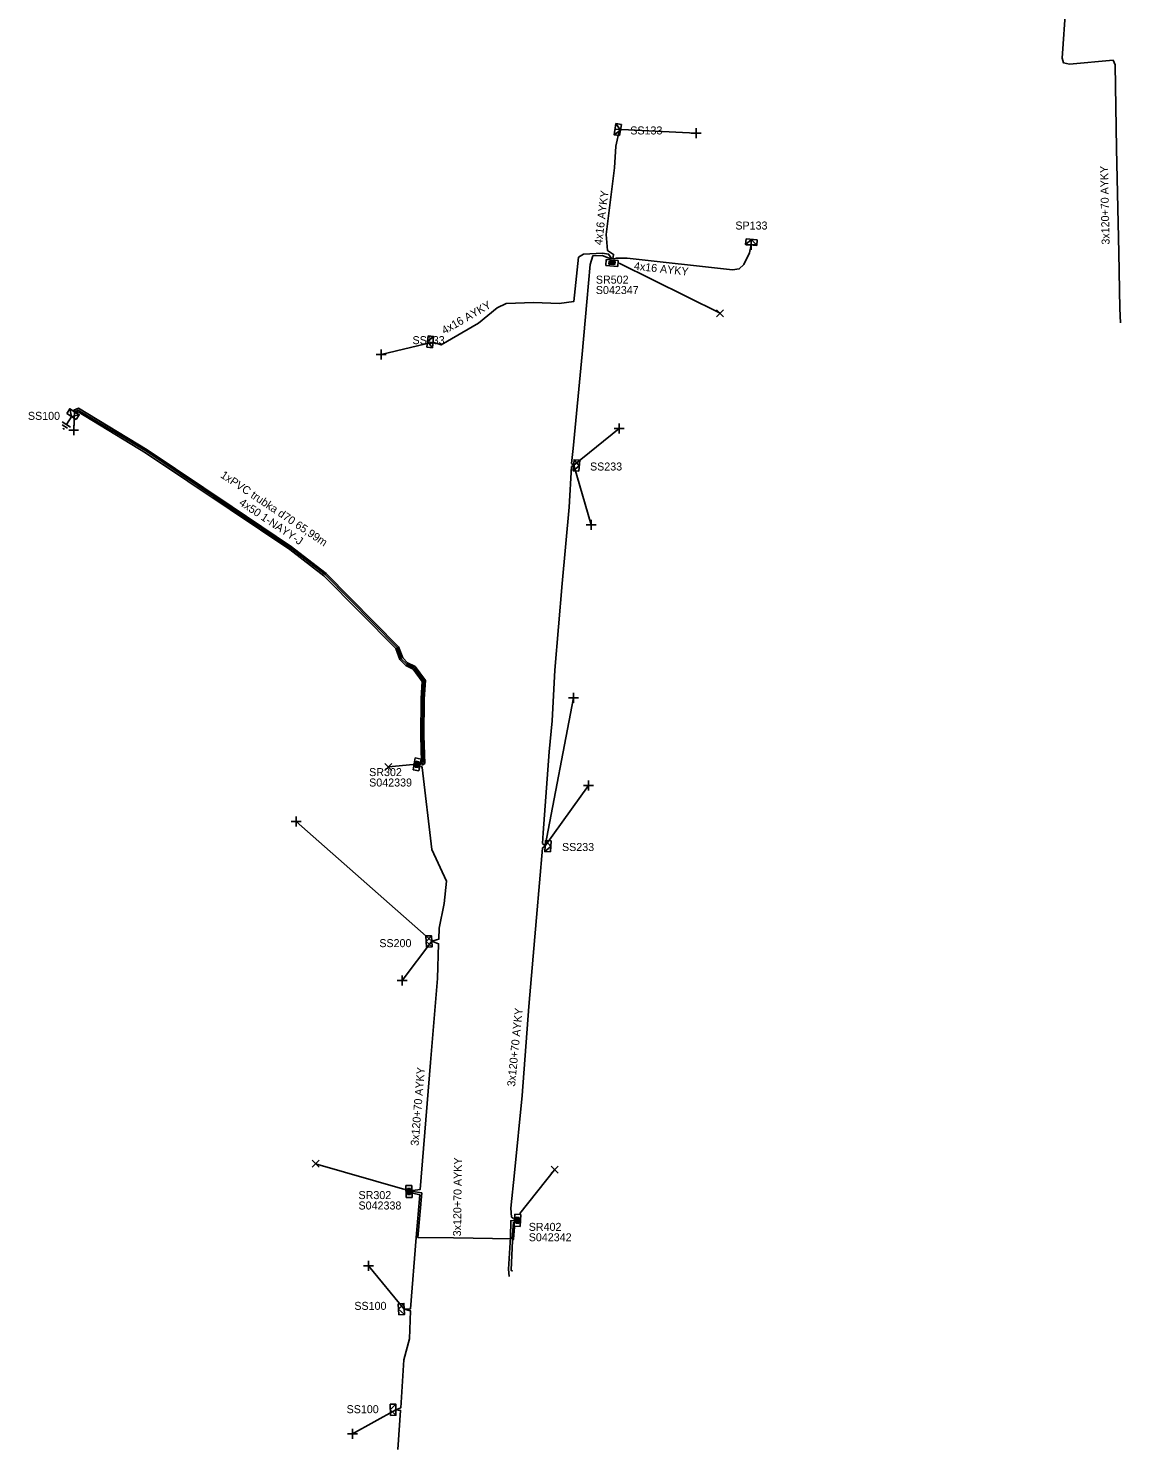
# Model space of a CAD drawing. Extents: x -737417 to -734469, y -1145580 to -1142703.
# Drawn here: x -736731.5 to -736594.9, y -1144630.5 to -1144452.9 of the extents above; entities that cross this region are included whole.
import ezdxf

# ---------------------------------------------------------------- set-up
doc = ezdxf.new("R2010")
doc.units = 0
for name, color, linetype in [('Vrstva 1', 7, 'Continuous'), ('Vrstva 14', 7, 'Continuous'), ('Vrstva 15', 7, 'Continuous'), ('Vrstva 20', 7, 'Continuous'), ('Vrstva 21', 7, 'Continuous'), ('Vrstva 28', 7, 'Continuous'), ('Vrstva 29', 7, 'Continuous'), ('Vrstva 30', 7, 'Continuous'), ('Vrstva 31', 7, 'Continuous'), ('Vrstva 33', 7, 'Continuous'), ('Vrstva 34', 7, 'Continuous'), ('Vrstva 5', 7, 'Continuous'), ('Vrstva 52', 7, 'Continuous'), ('Vrstva 54', 7, 'Continuous'), ('Vrstva 59', 7, 'Continuous'), ('Vrstva 6', 7, 'Continuous'), ('Vrstva 8', 7, 'Continuous'), ('Vrstva 9', 7, 'Continuous')]:
    doc.layers.add(name, color=color, linetype=linetype)

# ---------------------------------------------------------------- blocks, each defined once
blk = doc.blocks.new('NN800')
at = {"layer": 'Vrstva 1'}
for points in [[(-0.44, 0.44), (0.44, -0.44)], [(-0.44, -0.44), (0.44, 0.44)]]:
    blk.add_lwpolyline(points, dxfattribs=at)
blk = doc.blocks.new('NN620')
at = {"layer": 'Vrstva 8'}
for points in [[(0.75, 0), (-0.75, 0)], [(-0.75, 0), (-0.75, -0.75)], [(0.75, -0.75), (0.75, 0)], [(-0.75, -0.75), (0.75, -0.75)], [(0.37, -0.18), (-0.38, -0.18)], [(-0.38, -0.18), (-0.38, -0.56)], [(-0.38, -0.56), (0.37, -0.56)], [(0.32, -0.23), (-0.33, -0.23)], [(-0.33, -0.23), (-0.33, -0.51)], [(-0.33, -0.51), (0.32, -0.51)], [(0.27, -0.27), (-0.28, -0.27)], [(-0.28, -0.27), (-0.28, -0.46)], [(-0.28, -0.46), (0.27, -0.46)], [(0.23, -0.32), (-0.23, -0.32)], [(-0.23, -0.32), (-0.23, -0.42)], [(-0.23, -0.42), (0.23, -0.42)], [(-0.19, -0.37), (0.19, -0.37)], [(0.23, -0.42), (0.23, -0.32)], [(0.27, -0.46), (0.27, -0.27)], [(0.32, -0.51), (0.32, -0.23)], [(0.37, -0.56), (0.37, -0.18)]]:
    blk.add_lwpolyline(points, dxfattribs=at)
blk = doc.blocks.new('NN630')
at = {"layer": 'Vrstva 9'}
for points in [[(0, -0.7), (-0.7, 0)], [(-0.7, -0.7), (-0.7, 0), (0.7, 0), (0.7, -0.7)], [(-0.7, -0.7), (0.7, -0.7)], [(0, -0.7), (0.7, 0)]]:
    blk.add_lwpolyline(points, dxfattribs=at)
blk = doc.blocks.new('NN810')
at = {"layer": 'Vrstva 14'}
for points in [[(0, -0.64), (0, -1.89)], [(0.63, -1.89), (-0.62, -1.89)], [(0.39, -2.2), (-0.4, -2.2)], [(0, -2.52), (-0.12, -2.52)], [(0.14, -2.52), (0, -2.52)]]:
    blk.add_lwpolyline(points, dxfattribs=at)

msp = doc.modelspace()

# ---------------------------------------------------------------- linework, layer by layer
at = {"layer": 'Vrstva 20'}
msp.add_lwpolyline([(-736725.63, -1144500.97), (-736725.79, -1144500.61), (-736725.22, -1144500.37), (-736716.61, -1144505.57), (-736706.01, -1144512.68), (-736698.56, -1144517.67), (-736694.26, -1144520.99), (-736685.19, -1144530.16), (-736684.68, -1144531.55), (-736684.06, -1144532.17), (-736683.12, -1144532.62), (-736681.83, -1144534.38), (-736681.98, -1144536.65), (-736682.02, -1144541.27), (-736681.93, -1144544.74), (-736682.18, -1144544.93), (-736682.42, -1144544.61), (-736682.33, -1144544.54), (-736682.42, -1144541.27), (-736682.38, -1144536.63), (-736682.23, -1144534.5), (-736683.38, -1144532.94), (-736684.3, -1144532.51), (-736685.02, -1144531.77), (-736685.53, -1144530.38), (-736694.52, -1144521.29), (-736698.8, -1144517.99), (-736706.23, -1144513.02), (-736716.83, -1144505.91), (-736725.26, -1144500.81)], close=True, dxfattribs=at)
at = {"layer": 'Vrstva 5'}
for points in [[(-736594.93, -1144489.69), (-736595.02, -1144487.91), (-736595.16, -1144480.95), (-736595.43, -1144467.91), (-736595.62, -1144457.47), (-736595.88, -1144456.88), (-736601.32, -1144457.36), (-736602.06, -1144457.22), (-736602.25, -1144456.63), (-736601.78, -1144450.05), (-736601.32, -1144447.49), (-736600.13, -1144443.42), (-736598.57, -1144440), (-736598.05, -1144438.72), (-736598.27, -1144438.36)], [(-736658.67, -1144481.69), (-736659.73, -1144481.27), (-736660.91, -1144481.32), (-736661.24, -1144482.38), (-736661.64, -1144487.07), (-736662.24, -1144493.62), (-736663.37, -1144505.4), (-736663.56, -1144507.25), (-736663.3, -1144507.49), (-736663.59, -1144507.64), (-736663.86, -1144512.7), (-736664.74, -1144522.26), (-736665.66, -1144533.09), (-736666, -1144539.42), (-736666.36, -1144543.27), (-736667.13, -1144553.42), (-736667.19, -1144554.74), (-736666.86, -1144555.05), (-736667.22, -1144555.31), (-736667.97, -1144563.97), (-736668.89, -1144575.1), (-736669.75, -1144586.22), (-736670.72, -1144595.89), (-736671.16, -1144600.32), (-736671.06, -1144601.42), (-736670.82, -1144601.59)], [(-736682.36, -1144544.82), (-736682.13, -1144544.64), (-736682.22, -1144541.27), (-736682.18, -1144536.64), (-736682.03, -1144534.44), (-736683.25, -1144532.78), (-736684.18, -1144532.34), (-736684.85, -1144531.66), (-736685.36, -1144530.27), (-736694.39, -1144521.14), (-736698.68, -1144517.83), (-736706.12, -1144512.85), (-736716.72, -1144505.74), (-736725.24, -1144500.59), (-736725.71, -1144500.79)], [(-736682.36, -1144545.04), (-736682.26, -1144545.23), (-736681.02, -1144555.48), (-736679.21, -1144559.46), (-736679.48, -1144562.24), (-736680.1, -1144565.3), (-736680.18, -1144566.71), (-736681.05, -1144566.96), (-736680.2, -1144567.27), (-736680.32, -1144571.62), (-736681.21, -1144582.09), (-736682.51, -1144597.99), (-736683.4, -1144598.08)], [(-736683.4, -1144598.41), (-736682.52, -1144598.65), (-736683, -1144603.95), (-736683.7, -1144612.87), (-736684.5, -1144612.91), (-736683.71, -1144613.13), (-736683.83, -1144616.62), (-736684.53, -1144619.27), (-736684.92, -1144625.25), (-736685.53, -1144625.48), (-736684.94, -1144625.57), (-736685.29, -1144630.47)], [(-736683.4, -1144598.23), (-736682.29, -1144598.4), (-736682.8, -1144603.95), (-736678.31, -1144604.03), (-736671.01, -1144604.14), (-736670.82, -1144602.04)], [(-736671.37, -1144608.84), (-736671.43, -1144607.91), (-736671.22, -1144603.91), (-736671.17, -1144601.88), (-736670.83, -1144601.85)]]:
    msp.add_lwpolyline(points, dxfattribs=at)
at = {"layer": 'Vrstva 52'}
for points in [[(-736658.41, -1144481.7), (-736658.32, -1144481.14), (-736659.07, -1144480.66), (-736659.23, -1144478.67), (-736658.22, -1144470.33), (-736658.02, -1144467.6), (-736657.59, -1144465.54), (-736658.14, -1144465.49)], [(-736658.28, -1144481.71), (-736657.96, -1144481.6), (-736656.63, -1144481.61), (-736643.46, -1144483.06), (-736642.61, -1144482.95), (-736642.05, -1144482.39), (-736641.31, -1144480.96), (-736641.11, -1144479.96)], [(-736658.54, -1144481.7), (-736658.93, -1144481.09), (-736659.71, -1144480.97), (-736662.07, -1144481.12), (-736662.7, -1144481.5), (-736663.29, -1144487.03), (-736665.11, -1144487.26), (-736668.28, -1144487.16), (-736671.75, -1144487.28), (-736672.87, -1144487.8), (-736675.22, -1144489.75), (-736679.87, -1144492.44), (-736680.89, -1144492.1)], [(-736670.68, -1144602.67), (-736670.81, -1144604.16), (-736670.97, -1144604.36), (-736671.12, -1144608.05), (-736670.95, -1144608.19)]]:
    msp.add_lwpolyline(points, dxfattribs=at)
at = {"layer": 'Vrstva 59'}
for points in [[(-736658.14, -1144465.49), (-736648, -1144466)], [(-736657.63, -1144482.25), (-736645, -1144488.5)], [(-736680.89, -1144492.1), (-736687.38, -1144493.63)], [(-736725.71, -1144500.79), (-736725.81, -1144503.11)], [(-736663.3, -1144507.49), (-736657.63, -1144502.88)], [(-736663.3, -1144507.49), (-736661.1, -1144514.92)], [(-736666.86, -1144555.05), (-736663.34, -1144536.55)], [(-736683.36, -1144544.85), (-736686.47, -1144545.18)], [(-736666.86, -1144555.05), (-736661.44, -1144547.5)], [(-736681.05, -1144566.96), (-736698, -1144552)], [(-736681.05, -1144566.96), (-736684.75, -1144571.87)], [(-736684.42, -1144597.96), (-736695.56, -1144594.75)], [(-736670.03, -1144600.95), (-736665.69, -1144595.5)], [(-736684.5, -1144612.91), (-736688.94, -1144607.5)], [(-736685.53, -1144625.48), (-736690.94, -1144628.5)]]:
    msp.add_lwpolyline(points, dxfattribs=at)

# ---------------------------------------------------------------- block references
at = {"layer": 'Vrstva 15', "rotation": -32.53332211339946}
msp.add_blockref('NN810', (-736725.71, -1144500.79), dxfattribs=at)
at = {"layer": 'Vrstva 28'}
for p, rotation in [((-736658.48, -1144481.83), -4.093386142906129), ((-736682.51, -1144544.93), -100.3069555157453), ((-736683.53, -1144598.21), -88.8060777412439), ((-736670.7, -1144601.79), 86.23996391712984)]:
    msp.add_blockref('NN620', p, dxfattribs=dict(at, rotation=rotation))
at = {"layer": 'Vrstva 31'}
for p, rotation in [((-736658.14, -1144465.49), 80.98679446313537), ((-736641.11, -1144479.96), 175.48842487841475), ((-736680.89, -1144492.1), -96.10519999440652), ((-736725.71, -1144500.79), -32.53332211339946), ((-736663.3, -1144507.49), 85.84177493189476), ((-736666.86, -1144555.05), 85.48008890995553), ((-736681.05, -1144566.96), -86.94440559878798), ((-736684.5, -1144612.91), -87.27786946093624), ((-736685.53, -1144625.48), -89.02002217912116)]:
    msp.add_blockref('NN630', p, dxfattribs=dict(at, rotation=rotation))
at = {"layer": 'Vrstva 34'}
for p, rotation in [((-736648, -1144466), 45), ((-736641.11, -1144479.96), 45), ((-736687.38, -1144493.63), 45), ((-736725.81, -1144503.11), 45), ((-736657.63, -1144502.88), 45), ((-736661.1, -1144514.92), 45), ((-736663.34, -1144536.55), 45), ((-736661.44, -1144547.5), 44.99999995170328), ((-736698, -1144552), 45), ((-736684.75, -1144571.87), 44.99999995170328), ((-736688.94, -1144607.5), 44.99999995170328), ((-736690.94, -1144628.5), 44.99999995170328)]:
    msp.add_blockref('NN800', p, dxfattribs=dict(at, rotation=rotation))
for p in [(-736645, -1144488.5), (-736686.47, -1144545.18), (-736695.56, -1144594.75), (-736665.69, -1144595.5)]:
    msp.add_blockref('NN800', p, dxfattribs=at)

# ---------------------------------------------------------------- texts
at = {"layer": 'Vrstva 21'}
msp.add_text('1xPVC trubka d70 65,99m', height=1, rotation=326.144, dxfattribs=at).set_placement((-736707.54, -1144508.93))
at = {"layer": 'Vrstva 29'}
for s, p in [('S042347', (-736660.53, -1144486.09)), ('S042339', (-736688.87, -1144547.62)), ('S042338', (-736690.2, -1144600.47)), ('S042342', (-736668.92, -1144604.44))]:
    msp.add_text(s, height=1, dxfattribs=at).set_placement(p)
at = {"layer": 'Vrstva 30'}
for s, p in [('SR502', (-736660.53, -1144484.79)), ('SR302', (-736688.87, -1144546.32)), ('SR302', (-736690.2, -1144599.17)), ('SR402', (-736668.92, -1144603.14))]:
    msp.add_text(s, height=1, dxfattribs=at).set_placement(p)
at = {"layer": 'Vrstva 33'}
for s, p in [('SS133', (-736656.23, -1144466.15)), ('SP133', (-736643.09, -1144478.03)), ('SS133', (-736683.45, -1144492.35)), ('SS100', (-736731.53, -1144501.81)), ('SS233', (-736661.26, -1144508.14)), ('SS233', (-736664.76, -1144555.68)), ('SS200', (-736687.6, -1144567.69)), ('SS100', (-736690.72, -1144613.01)), ('SS100', (-736691.69, -1144625.92))]:
    msp.add_text(s, height=1, dxfattribs=at).set_placement(p)
at = {"layer": 'Vrstva 54'}
for rotation, p in [(83.095, (-736659.76, -1144480.01)), (353.717, (-736655.8, -1144483.05)), (29.992, (-736679.45, -1144491.16))]:
    msp.add_text('4x16 AYKY', height=1, rotation=rotation, dxfattribs=at).set_placement(p)
at = {"layer": 'Vrstva 6'}
for s, rotation, p in [('3x120+70 AYKY', 91.186, (-736596.3, -1144479.91)), ('4x50 1-NAYY-J', 326.203, (-736705.22, -1144512.38)), ('3x120+70 AYKY', 84.272, (-736670.64, -1144585.15)), ('3x120+70 AYKY', 85.326, (-736682.7, -1144592.55)), ('3x120+70 AYKY', 89.273, (-736677.39, -1144603.83))]:
    msp.add_text(s, height=1, rotation=rotation, dxfattribs=at).set_placement(p)

doc.saveas('drawing.dxf')
